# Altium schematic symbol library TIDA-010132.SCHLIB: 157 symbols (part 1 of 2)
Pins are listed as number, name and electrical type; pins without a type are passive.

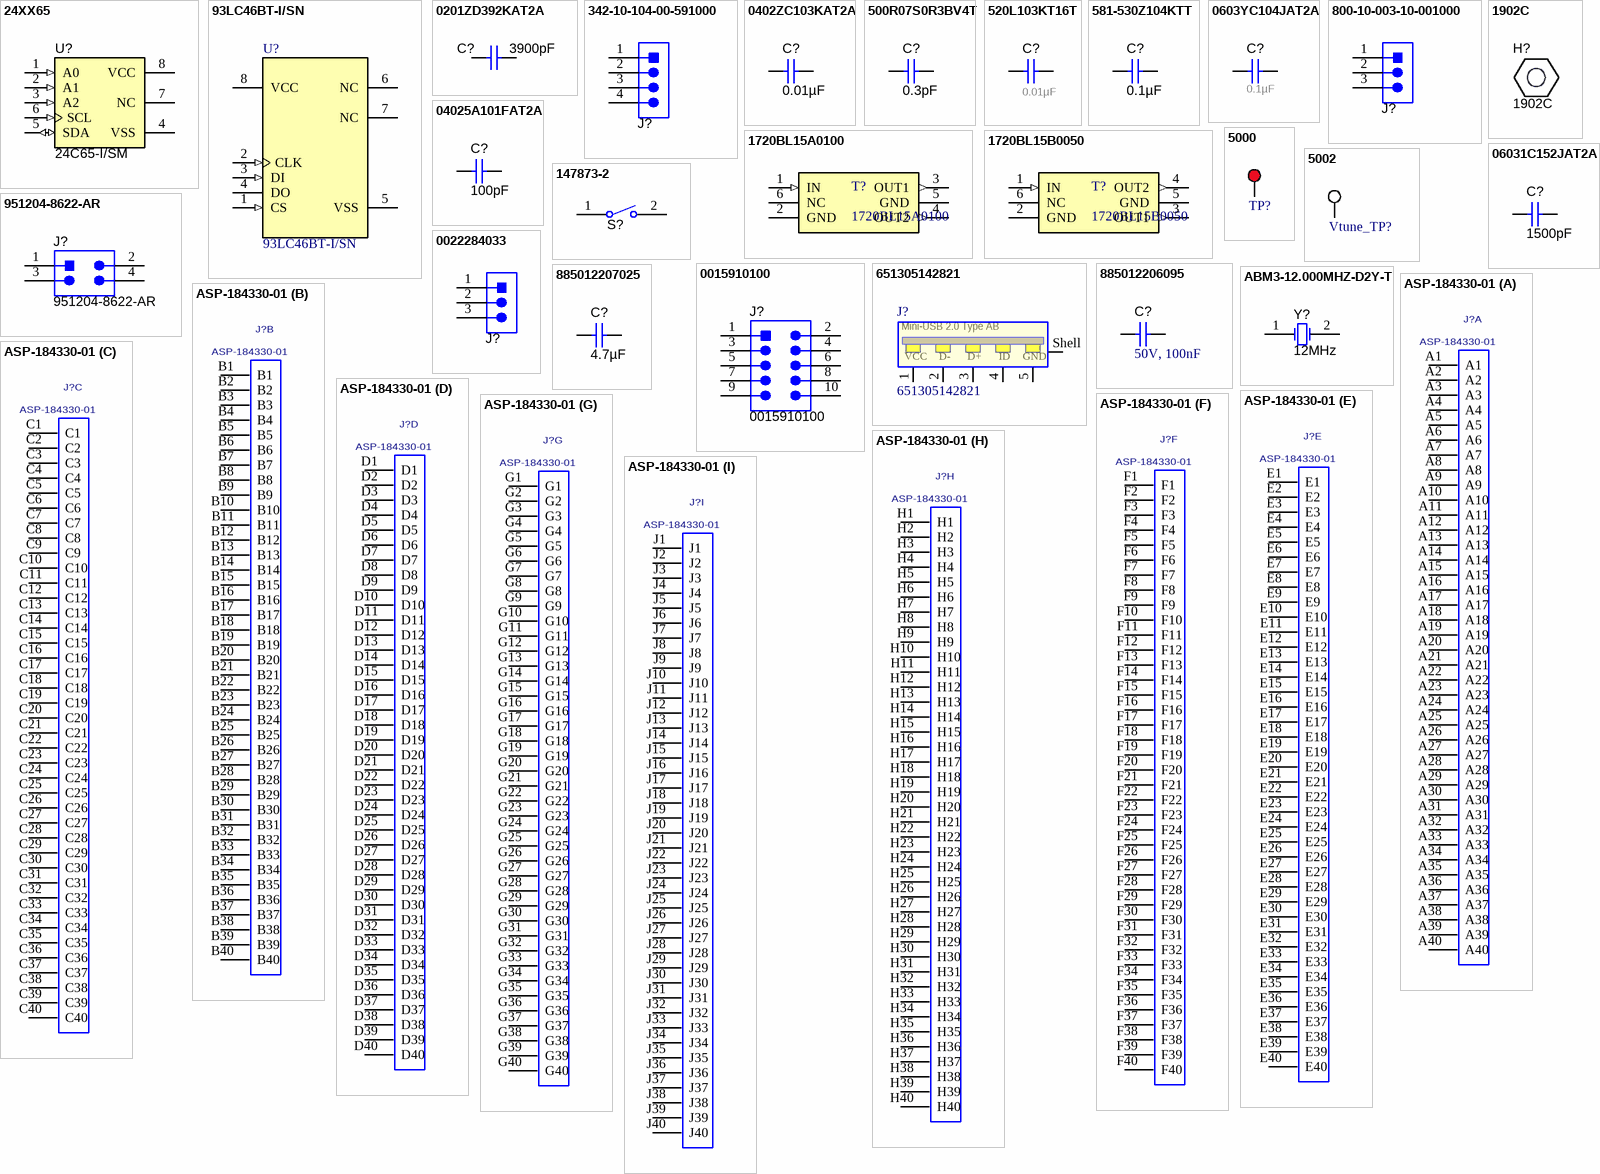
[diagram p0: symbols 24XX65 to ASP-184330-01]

## 24XX65
designator U?, comment 24C65-I/SM
64K I2C Smart Serial EEPROM, SOIC-8; Manufacturer: Microchip
footprint SOIC127P800X216-8N (SOIC, 8-Leads, Body 5.3x5.3mm (max), Pitch 1.27mm, IPC Medium Density)
footprint SOIC127P800X216-8L (SOIC, 8-Leads, Body 5.3x5.3mm (max), Pitch 1.27mm, IPC High Density)
footprint SOIC127P800X216-8M (SOIC, 8-Leads, Body 5.3x5.3mm (max), Pitch 1.27mm, IPC Low Density)
pins: 1 A0 (in), 2 A1 (in), 3 A2 (in), 4 VSS (power), 5 SDA (io), 6 SCL (in), 7 NC, 8 VCC (power)

## 93LC46BT-I/SN
designator U?
1K Microwire Compatible Serial EEPROM; Manufacturer: Microchip; SymbolCreator: Altium; SizeAreaWB_mm2: 55.131; SizeArea_mm2: 29.351; SizeX_mm: 5.99; SizeY_mm: 4.9; SizeZ_mm: 1.75
footprint SOIC-8
footprint SOIC-8M
footprint SOIC-8L
pins: 1 CS (in), 2 CLK (in), 3 DI (in), 4 DO (hiz), 5 VSS (power), 6 NC, 7 NC, 8 VCC (power)

## 0201ZD392KAT2A
designator C?  ValueDisplayed: 3900pF  (hidden comment: 0201ZD392KAT2A)
CAP, CERM, 3900 pF, 10 V, +/- 10%, X5R, 0201; Manufacturer: AVX; Polarized: N; CompType: Capacitor; Value: 3900pF; U/M: EA; Cap_F: 0.0000000039; Tolerance_%: 10; Value1: Unknown; Value2: 10V; TaMin_C: -55; TaMax_C: 85; Cap_Case: 0201; SizeArea_mm2: 0.18; SizeAreaWB_mm2: 2.08; SizeX_mm: 0.6; SizeY_mm: 0.3; SizeZ_mm: 0.26; AEC Category: Q200
signal-integrity model Cap
simulation model Cap
footprint 0201
footprint 0201M
footprint 0201L
footprint 0201_Silk
pins: 1, 2

## 342-10-104-00-591000
designator J?  (value not drawn)
Header, 100mil, 4x1, Gold, TH; Manufacturer: Mill-Max; SymbolCreator: a0412235; Green_Lifecycle: Active; Green_REACh: Passed
footprint Mill-Max_342-xx-104-00-591000
pins: 1, 2, 3, 4

## 0402ZC103KAT2A
designator C?  ValueDisplayed: 0.01µF  (hidden comment: 0402ZC103KAT2A)
CAP, CERM, 0.01 µF, 10 V,+/- 10%, X7R, 0402; Manufacturer: AVX; Polarized: N; CompType: Capacitor; Value: 0.01uF; U/M: EA; Cap_F: 0.00000001; Tolerance_%: 10; Value2: 10V; TaMin_C: -55; TaMax_C: 125; Cap_Case: 0402; SizeArea_mm2: 0.5; SizeAreaWB_mm2: 3; SizeX_mm: 1; SizeZ_mm: 0.6; AEC Category: Q200
signal-integrity model Cap
simulation model Cap
footprint 0402
footprint 0402M
footprint 0402L
footprint 0402S
pins: 1, 2

## 500R07S0R3BV4T
designator C?  ValueDisplayed: 0.3pF  (hidden comment: 500R07S0R3BV4T)
CAP, CERM, 0.3 pF, 50 V,+/- 30%, C0G/NP0, 0402; Manufacturer: Johanson Technology; Polarized: N; CompType: Capacitor; Value: 0.3pF; U/M: EA; Cap_F: 0.0000000000003; Tolerance_%: 30; Value1: Unknown; VDC_V: 50; Value2: 50V; TaMin_C: -55; TaMax_C: 125; Cap_Case: 0402; SizeArea_mm2: 0.5; SizeAreaWB_mm2: 3; SizeX_mm: 1; SizeZ_mm: 0.6; AEC Category: Q200
signal-integrity model Cap
simulation model Cap
footprint 0402
footprint 0402M
footprint 0402L
footprint 0402S
pins: 1, 2

## 520L103KT16T
designator C?  ValueDisplayed: 0.01µF  (hidden comment: 520L103KT16T)
CAP, CERM, 0.01 µF, 16 V, +/- 10%, X7R, 0402; Manufacturer: AT Ceramics; Polarized: N; CompType: Capacitor; Value: 0.01uF; U/M: EA; Cap_F: 0.00000001; Tolerance_%: 10; Value1: Unknown; VDC_V: 16; Value2: 16V; TaMin_C: -55; TaMax_C: 125; Cap_Case: 0402; AEC Category: Q200; SizeArea_mm2: 0.5; SizeAreaWB_mm2: 3; SizeX_mm: 1; SizeZ_mm: 0.65
signal-integrity model Cap
simulation model Cap
footprint 0402_065
footprint 0402_065M
footprint 0402_065L
footprint 0402_065S
pins: 1, 2

## 581-530Z104KTT
designator C?, comment ValueDisplayed: 0.1µF  (hidden comment: 530Z104KT10T)
Multilayer Ceramic Capacitors MLCC - SMD/SMT 10volts 0.1uF 10%; Manufacturer: ATC; Polarized: N; U/M: EA; Cap_F: 0.0000001; Tolerance_%: 10; Value1: Unknown; Value2: 10V; TempCo: X7S; TaMin_C: -55; TaMax_C: 125; Cap_Case: 0201; SizeArea_mm2: 0.18; SizeAreaWB_mm2: 2.08; SizeX_mm: 0.6; SizeY_mm: 0.3; SizeZ_mm: 0.26; AEC Category: Q200
signal-integrity model Cap
simulation model Cap
footprint 0201
footprint 0201M
footprint 0201L
footprint 0201_Silk
footprint 0201_afe
pins: 1, 2

## 0603YC104JAT2A
designator C?  ValueDisplayed: 0.1µF  (hidden comment: 0603YC104JAT2A)
CAP, CERM, 0.1uF, 16V, +/-5%, X7R, 0603; Manufacturer: AVX; Cap_Case: 0603; ESR_Ohm: 0.039; Polarized: N; TaMax_C: 125; TaMin_C: -55; Tolerance_%: 5; VDC_V: 16; Cap_F: 0.0000001; CompType: Capacitor; Value1: 0.039 ohm; U/M: EA
signal-integrity model Cap
simulation model Cap
footprint 0603
footprint 0603M
footprint 0603L
footprint 0603_HV
pins: 1, 2

## 800-10-003-10-001000
designator J?  (value not drawn)
Header, 100mil, 3x1, TH; Manufacturer: Mill-Max; SymbolCreator: a0799628
footprint Mill-Max_800-10-003-10-001000
pins: 1, 2, 3
3 alternate drawings of the same symbol

## 1720BL15A0100
designator T?
BALUN 625MHZ-2.8GHZ 50/100 0805; PartNumber: 1720BL15A0100E; Manufacturer: Johanson Technology Inc.
pins: 1 IN (in), 2 GND (power), 3 OUT1 (out), 4 OUT2 (out), 5 GND (power), 6 NC (hiz)

## 1720BL15B0050
designator T?
BALUN 625MHZ-2.8GHZ 50/50 0805; PartNumber: 1720BL15B0050E; Manufacturer: Johanson Technology Inc.
pins: 1 IN (in), 2 GND (power), 3 OUT1 (out), 4 OUT2 (out), 5 GND (power), 6 NC (hiz)

## 1902C
designator H?
Standoff, Hex, 0.5"L #4-40 Nylon; Manufacturer: Keystone; Green_Lifecycle: Active; Green_REACh: Passed; SymbolCreator: a0412235
footprint Keystone_1902C

## 04025A101FAT2A
designator C?  ValueDisplayed: 100pF  (hidden comment: 04025A101FAT2A)
CAP, CERM, 100 pF, 50 V, +/- 1%, C0G/NP0, 0402; Manufacturer: AVX; Polarized: N; CompType: Capacitor; Value: 100pF; U/M: EA; Cap_F: 0.0000000001; Tolerance_%: 1; Value1: Unknown; VDC_V: 50; Value2: 50V; TaMin_C: -55; TaMax_C: 125; Cap_Case: 0402; SizeArea_mm2: 0.5; SizeAreaWB_mm2: 3; SizeZ_mm: 0.6; AEC Category: Q200
signal-integrity model Cap
simulation model Cap
footprint 0402
footprint 0402M
footprint 0402L
footprint 0402S
pins: 1, 2

## 5000
designator TP?  (value not drawn)
Test Point, Miniature, Red, TH; Manufacturer: Keystone; CompType: Test Point Loop; ContactFinish: Silver; Green_Lifecycle: Active; Green_REACh: Passed
footprint Keystone5000
pins: 1

## 5002
designator Vtune_TP?  (value not drawn)
Test Point, Miniature, White, TH; Manufacturer: Keystone; CompType: Test Point Loop; ContactFinish: Silver; Green_Lifecycle: Active; Green_REACh: Passed
footprint Keystone5002
pins: 1

## 06031C152JAT2A
designator C?  ValueDisplayed: 1500pF  (hidden comment: 06031C152JAT2A)
CAP, CERM, 1500 pF, 100 V, +/- 5%, X7R, 0603; Manufacturer: AVX; Cap_Case: 0603; ESR_ohm: 0.229; Polarized: N; TaMax_C: 125; TaMin_C: -55; Tolerance_%: 5; VDC_V: 100; Cap_F: 0.0000000015; CompType: Capacitor; Value: 1500pF; Value1: 0.229 ohm; Value2: 100V; U/M: EA; AEC Category: Q200; SizeArea_mm2: 1.28; SizeAreaWB_mm2: 4.68; SizeX_mm: 1.6; SizeY_mm: 0.8; SizeZ_mm: 1
signal-integrity model Cap
simulation model Cap
footprint 0603
footprint 0603M
footprint 0603L
footprint 0603_HV
footprint 0603S
pins: 1, 2

## 147873-2
designator S?  (value not drawn)
Switch, SPST, Off-On, 50 mA,24V, SMD; Manufacturer: TE Connectivity; SymbolCreator: a0799628; SizeAreaWB_mm2: 48.4; SizeArea_mm2: 23.8; SizeX_mm: 6.8; SizeY_mm: 3.5; SizeZ_mm: 4.65; VDC_V: 24; PositionCount: 1; CurrentRating_mA: 50
footprint SW_147873-2
pins: 1, 2

## 951204-8622-AR
designator J?
Header, 2mm, 2x2, Gold, TH; Manufacturer: 3M; SymbolCreator: a0412235; Pitch_mm: 2; Gender: Male; Shrouded: N; Current_A: 1; Voltage_V: 1000; Cert_UL: Y
footprint 3M_951204-8622
pins: 1, 2, 3, 4

## 0015910100
designator J?
Header, 100mil, 5x2, SMT; Manufacturer: Molex; SymbolCreator: a0412235; Green_Lifecycle: Active; Green_REACh: Passed
footprint Molex_0015910100
pins: 1, 2, 3, 4, 5, 6, 7, 8, 9, 10

## 0022284033
designator J?  (value not drawn)
Header, 2.54mm, 3x1, Tin, TH; Manufacturer: Molex; SymbolCreator: a0799628; Pitch_mm: 2.54; Gender: Male; Shrouded: N; Row_Count: 1; Current_A: 4; Voltage_V: 250; Cert_UL: Y
footprint Molex_0022284033
pins: 1, 2, 3
3 alternate drawings of the same symbol

## 651305142821
designator J?
WR-COM Mini USB 2.0 Type AB SMT Horizontal 5 Contacts
footprint 651305142821 (5 pins)
pins: 1 VCC, 2 D-, 3 D+, 4 ID, 5 GND, Shell

## 885012206095
designator C?, comment 50V, 100nF
WCAP-CSGP Ceramic Capacitors, 0603, X7R, 50V, 100nF; Part Number: 885012206095; Manufacturer: Wurth Electronics Inc.; Rated Voltage: 50V DC
footprint 0603_1.6x0.8x0.8mm_Wave Soldering
footprint 0603_1.6x0.8x0.8mm_Reflow Soldering
pins: 1, 2

## 885012207025
designator C?  ValueDisplayed: 4.7µF  (hidden comment: 885012207025)
CAP, CERM, 4.7 µF, 10 V,+/- 10%, X7R, 0805; Manufacturer: Wurth Elektronik; Polarized: N; CompType: Capacitor; Value: 4.7uF; U/M: EA; Cap_F: 0.0000047; Tolerance_%: 10; Value2: 10V; TaMin_C: -55; TaMax_C: 125; Cap_Case: 0805; SizeArea_mm2: 2.5; SizeAreaWB_mm2: 6.75; SizeX_mm: 2; SizeY_mm: 1.25; SizeZ_mm: 1.45; AEC Category: Q200
signal-integrity model Cap
simulation model Cap
footprint 0805_HV
footprint 0805_HV1
footprint 0805
footprint 0805M
footprint 0805L
pins: 1, 2

## ABM3-12.000MHZ-D2Y-T
designator Y?  Frequency: 12MHz  (hidden comment: ABM3-12.000MHZ-D2Y-T)
Crystal, 12 MHz, 18 pF, SMD; Manufacturer: Abracon Corporation; SymbolCreator: a0412235; U/M: EA; TaMin_C: -40; TaMax_C: 85; Frequency Stability: ±30ppm
footprint XTAL_ABM3
pins: 1 OSC1, 2 OSC2

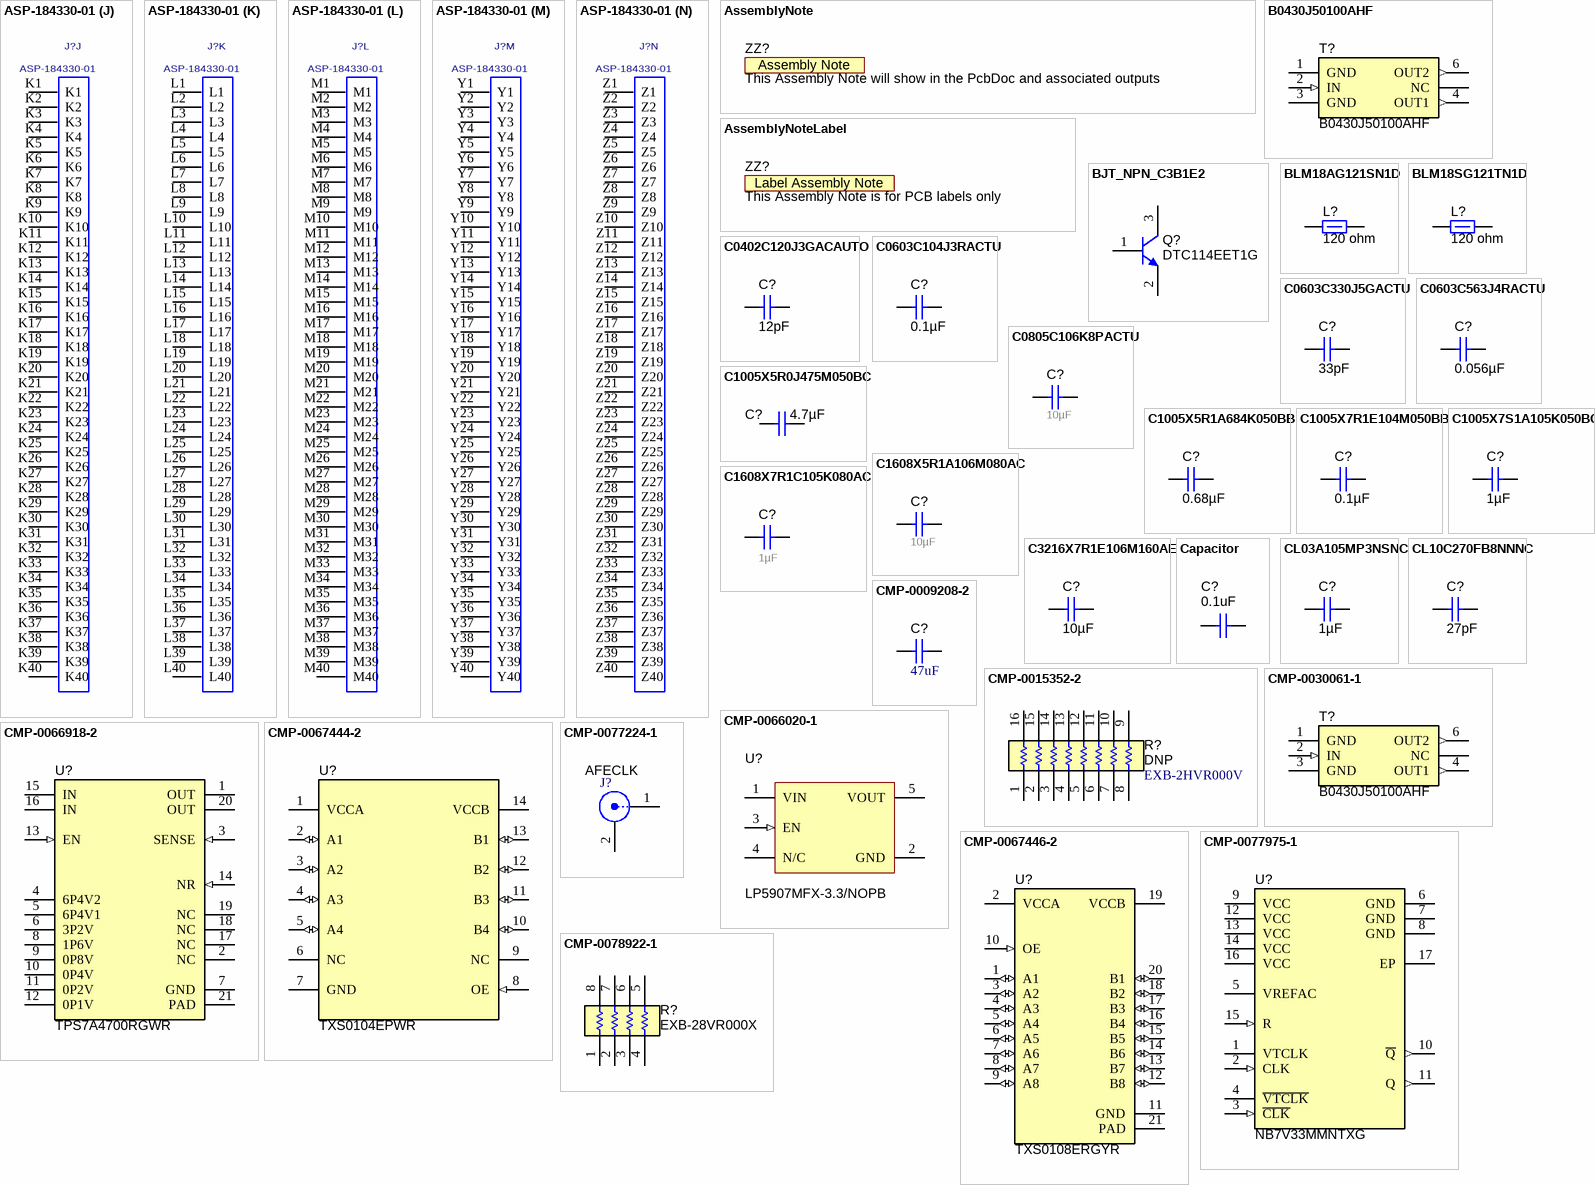
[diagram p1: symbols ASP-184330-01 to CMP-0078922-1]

## ASP-184330-01
designator J?
14 ROW .050 PITCH TERMINAL ARRAY ASM.; Manufacturer: SAMTEC
footprint ASP-184330-01 (Terminal Array, 1.27mm, 40x14, SMT)
part A pins: A1, A2, A3, A4, A5, A6, A7, A8, A9, A10, A11, A12, A13, A14, A15, A16, A17, A18, A19, A20, A21, A22, A23, A24, A25, A26, A27, A28, A29, A30, A31, A32, A33, A34, A35, A36, A37, A38, A39, A40
part B pins: B1, B2, B3, B4, B5, B6, B7, B8, B9, B10, B11, B12, B13, B14, B15, B16, B17, B18, B19, B20, B21, B22, B23, B24, B25, B26, B27, B28, B29, B30, B31, B32, B33, B34, B35, B36, B37, B38, B39, B40
part C pins: C1, C2, C3, C4, C5, C6, C7, C8, C9, C10, C11, C12, C13, C14, C15, C16, C17, C18, C19, C20, C21, C22, C23, C24, C25, C26, C27, C28, C29, C30, C31, C32, C33, C34, C35, C36, C37, C38, C39, C40
part D pins: D1, D2, D3, D4, D5, D6, D7, D8, D9, D10, D11, D12, D13, D14, D15, D16, D17, D18, D19, D20, D21, D22, D23, D24, D25, D26, D27, D28, D29, D30, D31, D32, D33, D34, D35, D36, D37, D38, D39, D40
part E pins: E1, E2, E3, E4, E5, E6, E7, E8, E9, E10, E11, E12, E13, E14, E15, E16, E17, E18, E19, E20, E21, E22, E23, E24, E25, E26, E27, E28, E29, E30, E31, E32, E33, E34, E35, E36, E37, E38, E39, E40
part F pins: F1, F2, F3, F4, F5, F6, F7, F8, F9, F10, F11, F12, F13, F14, F15, F16, F17, F18, F19, F20, F21, F22, F23, F24, F25, F26, F27, F28, F29, F30, F31, F32, F33, F34, F35, F36, F37, F38, F39, F40
part G pins: G1, G2, G3, G4, G5, G6, G7, G8, G9, G10, G11, G12, G13, G14, G15, G16, G17, G18, G19, G20, G21, G22, G23, G24, G25, G26, G27, G28, G29, G30, G31, G32, G33, G34, G35, G36, G37, G38, G39, G40
part H pins: H1, H2, H3, H4, H5, H6, H7, H8, H9, H10, H11, H12, H13, H14, H15, H16, H17, H18, H19, H20, H21, H22, H23, H24, H25, H26, H27, H28, H29, H30, H31, H32, H33, H34, H35, H36, H37, H38, H39, H40
part I pins: J1, J2, J3, J4, J5, J6, J7, J8, J9, J10, J11, J12, J13, J14, J15, J16, J17, J18, J19, J20, J21, J22, J23, J24, J25, J26, J27, J28, J29, J30, J31, J32, J33, J34, J35, J36, J37, J38, J39, J40
part J pins: K1, K2, K3, K4, K5, K6, K7, K8, K9, K10, K11, K12, K13, K14, K15, K16, K17, K18, K19, K20, K21, K22, K23, K24, K25, K26, K27, K28, K29, K30, K31, K32, K33, K34, K35, K36, K37, K38, K39, K40
part K pins: L1, L2, L3, L4, L5, L6, L7, L8, L9, L10, L11, L12, L13, L14, L15, L16, L17, L18, L19, L20, L21, L22, L23, L24, L25, L26, L27, L28, L29, L30, L31, L32, L33, L34, L35, L36, L37, L38, L39, L40
part L pins: M1, M2, M3, M4, M5, M6, M7, M8, M9, M10, M11, M12, M13, M14, M15, M16, M17, M18, M19, M20, M21, M22, M23, M24, M25, M26, M27, M28, M29, M30, M31, M32, M33, M34, M35, M36, M37, M38, M39, M40
part M pins: Y1, Y2, Y3, Y4, Y5, Y6, Y7, Y8, Y9, Y10, Y11, Y12, Y13, Y14, Y15, Y16, Y17, Y18, Y19, Y20, Y21, Y22, Y23, Y24, Y25, Y26, Y27, Y28, Y29, Y30, Y31, Y32, Y33, Y34, Y35, Y36, Y37, Y38, Y39, Y40
part N pins: Z1, Z2, Z3, Z4, Z5, Z6, Z7, Z8, Z9, Z10, Z11, Z12, Z13, Z14, Z15, Z16, Z17, Z18, Z19, Z20, Z21, Z22, Z23, Z24, Z25, Z26, Z27, Z28, Z29, Z30, Z31, Z32, Z33, Z34, Z35, Z36, Z37, Z38, Z39, Z40

## AssemblyNote
designator ZZ?, comment This Assembly Note will show in the PcbDoc and associated outputs  (no BOM)
SymbolCreator: codlsc
footprint AssemblyNote

## AssemblyNoteLabel
designator ZZ?, comment This Assembly Note is for PCB labels only  (no BOM)
SymbolCreator: a0412235
footprint AssemblyNoteLabel

## B0430J50100AHF
designator T?
Transformer, Multi-layer balun, SMD; Manufacturer: Anaren; Green_REACh: Incomplete; Green_Lifecycle: Not Set
footprint B0430J50100AHF (Anaren Ultra Low Profile 0805 Balun 50  to 100  Balanced)
pins: 1 GND (power), 2 IN (in), 3 GND (power), 4 OUT1 (out), 5 NC (hiz), 6 OUT2 (out)

## BJT_NPN_C3B1E2
designator Q?, comment DTC114EET1G
Transistor, NPN, 50 V, 0.1 A, AEC-Q101, SOT-416; Manufacturer: ON Semiconductor; TaMax_C: 150°C; Value2: 60; Value1: 0.1 A; Vcesat1_V: 2.5dV; SizeX_mm: 1.6; TaMin_C: -55°C; IcRated_A: 1dA; CompType: BJT; SizeZ_mm: 0.95; AEC Qualified: Y; Value: 50 V; SizeArea_mm2: 2.56; NPN: 1; Vceo_V: 50V; PNP: 0; AEC Category: Q101; SizeAreaWB_mm2: 6.76; U/M: EA
footprint SOT-416 (NXP recommended footprint.)
pins: 1 B, 2 E, 3 C

## BLM18AG121SN1D
designator L?  ValueDisplayed: 120 ohm  (hidden comment: BLM18AG121SN1D)
Ferrite Bead, 120 ohm @ 100 MHz, 0.5 A, 0603; Manufacturer: MuRata; Value: 120 ohm; Imax_A: 0.5; DCR_ohm: 0.18; Value1: 0.18 ohm; Value2: 0.5A; SizeAreaWB_mm2: 4.68; SizeArea_mm2: 1.28; SizeX_mm: 1.6; SizeY_mm: 0.8; SizeZ_mm: 1; ZTyp@100MHz_Ohm: 120
footprint 0603
footprint 0603M
footprint 0603L
footprint 0603_HV
footprint 0603S
pins: 1, 2

## BLM18SG121TN1D
designator L?  ValueDisplayed: 120 ohm  (hidden comment: BLM18SG121TN1D)
Ferrite Bead, 120 ohm @ 100 MHz, 3 A, 0603; Manufacturer: MuRata; Value: 120 ohm; Imax_A: 3; DCR_ohm: 0.025; Value1: 0.025 ohm; Value2: 3A; SizeAreaWB_mm2: 4.68; SizeArea_mm2: 1.28; SizeX_mm: 1.6; SizeY_mm: 0.8; SizeZ_mm: 1; ZTyp@100MHz_Ohm: 120
footprint 0603
footprint 0603M
footprint 0603L
footprint 0603_HV
footprint 0603S
pins: 1, 2

## C0402C120J3GACAUTO
designator C?  ValueDisplayed: 12pF  (hidden comment: C0402C120J3GACAUTO)
CAP, CERM, 12 pF, 25 V, +/- 5%, C0G/NP0, AEC-Q200 Grade 1, 0402; Manufacturer: Kemet; Polarized: N; CompType: Capacitor; Value: 12pF; U/M: EA; Cap_F: 0.000000000012; Tolerance_%: 5; Value1: Unknown; VDC_V: 25; Value2: 25V; TaMin_C: -55; TaMax_C: 125; Cap_Case: 0402; SizeArea_mm2: 0.5; SizeAreaWB_mm2: 3; SizeX_mm: 1; SizeZ_mm: 0.6; AEC Category: Q200; AEC Qualified: Y
signal-integrity model Cap
simulation model Cap
footprint 0402
footprint 0402M
footprint 0402L
footprint 0402S
pins: 1, 2

## C0603C104J3RACTU
designator C?  ValueDisplayed: 0.1µF  (hidden comment: C0603C104J3RACTU)
CAP, CERM, 0.1uF, 25V, +/-5%, X7R, 0603; Manufacturer: Kemet; Cap_Case: 0603; Polarized: N; TaMax_C: 125; TaMin_C: -55; Tolerance_%: 5; VDC_V: 25; Cap_F: 0.0000001; CompType: Capacitor; Value1: Unknown; U/M: EA
signal-integrity model Cap
simulation model Cap
footprint 0603
footprint 0603M
footprint 0603L
footprint 0603_HV
pins: 1, 2

## C0603C330J5GACTU
designator C?  ValueDisplayed: 33pF  (hidden comment: C0603C330J5GACTU)
CAP, CERM, 33pF, 50V, +/-5%, C0G/NP0, 0603; Manufacturer: Kemet; Cap_Case: 0603; Polarized: N; TaMax_C: 125; TaMin_C: -55; Tolerance_%: 5; VDC_V: 50; Cap_F: 0.000000000033; CompType: Capacitor; U/M: EA; Value1: Unknown
signal-integrity model Cap
simulation model Cap
footprint 0603
footprint 0603M
footprint 0603L
footprint 0603_HV
pins: 1, 2

## C0603C563J4RACTU
designator C?  ValueDisplayed: 0.056µF  (hidden comment: C0603C563J4RACTU)
CAP, CERM, 0.056 µF, 16 V, +/- 5%, X7R, 0603; Manufacturer: Kemet; Cap_Case: 0603; Polarized: N; TaMax_C: 125; TaMin_C: -55; Tolerance_%: 5; VDC_V: 16; Cap_F: 0.000000056; CompType: Capacitor; Value: 0.056uF; Value1: Unknown; Value2: 16V; U/M: EA; AEC Category: Q200; SizeArea_mm2: 1.28; SizeAreaWB_mm2: 4.68; SizeX_mm: 1.6; SizeY_mm: 0.8; SizeZ_mm: 1
signal-integrity model Cap
simulation model Cap
footprint 0603
footprint 0603M
footprint 0603L
footprint 0603_HV
footprint 0603S
pins: 1, 2

## C0805C106K8PACTU
designator C?  ValueDisplayed: 10µF  (hidden comment: C0805C106K8PACTU)
CAP, CERM, 10uF, 10V, +/-10%, X5R, 0805; Manufacturer: Kemet; Cap_Case: 0805; ESR_Ohm: 0.003; IRMS_A: 11.43; Polarized: N; TaMax_C: 85; TaMin_C: -55; Tolerance_%: 10; Cap_F: 0.00001; CompType: Capacitor; U/M: EA; Value1: 0.003 ohm
signal-integrity model Cap
simulation model Cap
footprint 0805_HV
footprint 0805
footprint 0805M
footprint 0805L
pins: 1, 2

## C1005X5R0J475M050BC
designator C?  ValueDisplayed: 4.7µF  (hidden comment: C1005X5R0J475M050BC)
CAP, CERM, 4.7 µF, 6.3 V, +/- 20%, X5R, 0402; Manufacturer: TDK; Polarized: N; CompType: Capacitor; Value: 4.7uF; U/M: EA; Cap_F: 0.0000047; Tolerance_%: 20; Value1: Unknown; VDC_V: 6.3; Value2: 6.3V; TaMin_C: -55; TaMax_C: 85; Cap_Case: 0402; SizeArea_mm2: 0.5; SizeAreaWB_mm2: 3; SizeX_mm: 1; SizeZ_mm: 0.6; AEC Category: Q200
signal-integrity model Cap
simulation model Cap
footprint 0402
footprint 0402M
footprint 0402L
footprint 0402S
pins: 1, 2

## C1005X5R1A684K050BB
designator C?  ValueDisplayed: 0.68µF  (hidden comment: C1005X5R1A684K050BB)
CAP, CERM, 0.68 µF, 10 V, +/- 10%, X5R, 0402; Manufacturer: TDK; Polarized: N; CompType: Capacitor; Value: 0.68uF; U/M: EA; Cap_F: 0.00000068; Tolerance_%: 10; Value1: Unknown; Value2: 10V; TaMin_C: -55; TaMax_C: 85; Cap_Case: 0402; SizeArea_mm2: 0.5; SizeAreaWB_mm2: 3; SizeX_mm: 1; SizeZ_mm: 0.6; AEC Category: Q200
signal-integrity model Cap
simulation model Cap
footprint 0402
footprint 0402M
footprint 0402L
footprint 0402S
pins: 1, 2

## C1005X7R1E104M050BB
designator C?  ValueDisplayed: 0.1µF  (hidden comment: C1005X7R1E104M050BB)
CAP, CERM, 0.1 µF, 25 V, +/- 20%, X7R, 0402; Manufacturer: TDK; Cap_Case: 0402; Polarized: N; TaMax_C: 125; TaMin_C: -55; Tolerance_%: 20; VDC_V: 25; Cap_F: 0.0000001; CompType: Capacitor; Value: 0.1uF; Value1: Unknown; Value2: 25V; U/M: EA; SizeArea_mm2: 0.5; SizeAreaWB_mm2: 3; SizeX_mm: 1; SizeZ_mm: 0.6; AEC Category: Q200
signal-integrity model Cap
simulation model Cap
footprint 0402
footprint 0402M
footprint 0402L
footprint 0402S
pins: 1, 2

## C1005X7S1A105K050BC
designator C?  ValueDisplayed: 1µF  (hidden comment: C1005X7S1A105K050BC)
CAP, CERM, 1 µF, 10 V, +/- 10%, X7S, 0402; Manufacturer: TDK; Polarized: N; CompType: Capacitor; Value: 1uF; U/M: EA; Cap_F: 0.000001; Tolerance_%: 10; ESR_ohm: 0.011416; Value1: 0.011416 ohm; Value2: 10V; IRMS_A: 1.483; TaMin_C: -55; TaMax_C: 125; Cap_Case: 0402; SizeArea_mm2: 0.5; SizeAreaWB_mm2: 3; SizeX_mm: 1; SizeZ_mm: 0.6; AEC Category: Q200
signal-integrity model Cap
simulation model Cap
footprint 0402
footprint 0402M
footprint 0402L
footprint 0402S
pins: 1, 2

## C1608X5R1A106M080AC
designator C?  ValueDisplayed: 10µF  (hidden comment: C1608X5R1A106M080AC)
CAP, CERM, 10 µF, 10 V, +/- 20%, X5R, 0603; Manufacturer: TDK; Cap_Case: 0603; ESR_ohm: 0.0078; IRMS_A: 1.85; Polarized: N; TaMax_C: 85; TaMin_C: -55; Tolerance_%: 20; VDC_V: 10; Cap_F: 0.00001; CompType: Capacitor; Value: 10uF; U/M: EA; Value1: 0.0078 ohm; Value2: 10V; AEC Category: Q200
signal-integrity model Cap
simulation model Cap
footprint 0603
footprint 0603M
footprint 0603L
footprint 0603_HV
footprint 0603S
pins: 1, 2

## C1608X7R1C105K080AC
designator C?  ValueDisplayed: 1µF  (hidden comment: C1608X7R1C105K080AC)
CAP, CERM, 1 µF, 16 V, +/- 10%, X7R, 0603; Manufacturer: TDK; Cap_Case: 0603; ESR_ohm: 0.0057; Polarized: N; TaMax_C: 125; TaMin_C: -55; Tolerance_%: 10; VDC_V: 16; Cap_F: 0.000001; CompType: Capacitor; Value: 1uF; Value1: 0.0057 ohm; Value2: 16V; U/M: EA; SizeArea_mm2: 1.28; SizeAreaWB_mm2: 4.68; SizeX_mm: 1.6; SizeY_mm: 0.8; SizeZ_mm: 1; AEC Category: Q200
signal-integrity model Cap
simulation model Cap
footprint 0603
footprint 0603M
footprint 0603L
footprint 0603_HV
footprint 0603S
pins: 1, 2

## C3216X7R1E106M160AE
designator C?  ValueDisplayed: 10µF  (hidden comment: C3216X7R1E106M160AE)
CAP, CERM, 10 µF, 25 V, +/- 20%, X7R, 1206_190; Manufacturer: TDK; Polarized: N; CompType: Capacitor; Value: 10uF; U/M: EA; Cap_F: 0.00001; Tolerance_%: 20; Value1: Unknown; VDC_V: 25; Value2: 25V; TaMin_C: -55; TaMax_C: 125; Cap_Case: 1206; SizeArea_mm2: 5.12; SizeAreaWB_mm2: 10.92; SizeX_mm: 3.2; SizeY_mm: 1.6; SizeZ_mm: 1.9; AEC Category: Q200
signal-integrity model Cap
simulation model Cap
footprint 1206_190
footprint 1206_190M
footprint 1206_190L
pins: 1, 2

## Capacitor
designator C?, comment ValueDisplayed: 0.1uF  (hidden comment: 550L104KCAT)
CAP, CERM, 0.1 uF, 16 V, +/- 10%, Unknown, 0402; Manufacturer: AT Ceramics; TaMin_C: -55°C; Polarized: N; SizeAreaWB_mm2: 3; U/M: EA; Value: 0.1uF; TaMax_C: 125°C; SizeZ_mm: 0.65; SizeX_mm: 1; SizeY_mm: 0.5; Cap_Case: 0402; Value2: 16V; CompType: Capacitor; Cap_F: 100nF; AEC Category: Q200
footprint 0402_065 (0402)
footprint 0402_065S (Based on C0402S footprint from PADS legacy)
footprint 0402_065L (0402)
footprint 0402_065M (0402)
pins: 1, 2

## CL03A105MP3NSNC
designator C?  ValueDisplayed: 1µF  (hidden comment: CL03A105MP3NSNC)
CAP, CERM, 1 µF, 10 V,+/- 20%, X5R, 0201; Manufacturer: Samsung Electro-Mechanics; Polarized: N; CompType: Capacitor; Value: 1uF; U/M: EA; Cap_F: 0.000001; Tolerance_%: 20; VDC_V: 10; Value2: 10V; TaMin_C: -55; TaMax_C: 85; Cap_Case: 0201; SizeArea_mm2: 0.18; SizeAreaWB_mm2: 2.08; SizeX_mm: 0.6; SizeY_mm: 0.3; SizeZ_mm: 0.26; AEC Category: Q200; Green_Lifecycle: Active; Green_REACh: Passed
signal-integrity model Cap
simulation model Cap
footprint 0201
footprint 0201M
footprint 0201L
footprint 0201_Silk
pins: 1, 2

## CL10C270FB8NNNC
designator C?  ValueDisplayed: 27pF  (hidden comment: CL10C270FB8NNNC)
CAP, CERM, 27 pF, 50 V,+/- 1%, C0G/NP0, 0603; Manufacturer: Samsung Electro-Mechanics; Polarized: N; CompType: Capacitor; Value: 27pF; U/M: EA; Cap_F: 0.000000000027; Tolerance_%: 1; VDC_V: 50; Value2: 50V; TaMin_C: -55; TaMax_C: 125; Cap_Case: 0603; SizeArea_mm2: 1.28; SizeAreaWB_mm2: 4.68; SizeX_mm: 1.6; SizeY_mm: 0.8; AEC Category: Q200; Green_Lifecycle: Active; Green_REACh: Passed
signal-integrity model Cap
simulation model Cap
footprint 0603
footprint 0603M
footprint 0603L
footprint 0603_HV
footprint 0603S
pins: 1, 2

## CMP-0009208-2
designator C?, comment value 47uF  (hidden comment: GRM32ER61A476KE20L)
CAP, CERM, 47 uF, 10 V, +/- 10%, X5R, 1210; Manufacturer: MuRata; TaMin_C: -55°C; ESR_ohm: 1m; Polarized: N; SizeAreaWB_mm2: 14.7; Value1: 0.001 ohm; U/M: EA; TaMax_C: 85°C; SizeZ_mm: 2.7; SizeX_mm: 3.2; SizeY_mm: 2.5; Cap_Case: 1210; Value2: 10V; SizeArea_mm2: 8; CompType: Capacitor; Cap_F: 47µF; AEC Category: Q200
footprint 1210_270 (1210)
footprint 1210_270L (1210)
footprint 1210_270M (1210)
pins: 1, 2

## CMP-0015352-2
designator R?, comment DNP  PartNumber: EXB-2HVR000V
RES, 0, 5%, 0.0625 W, Resistor Array - 8x1; Manufacturer: Panasonic; Power_W: 62.5mW; TempCo: ppm/C; Value_Code: 0000; U/M: EA; Value: 0; EIA_Code: E24; AEC Category: Q200
footprint RESCAXS_EXB-2HV (Panasonic Resistor Array)
pins: 1, 2, 3, 4, 5, 6, 7, 8, 9, 10, 11, 12, 13, 14, 15, 16

## CMP-0030061-1
designator T?, comment B0430J50100AHF
Transformer, Multi-layer balun, SMD; Manufacturer: Anaren; Green_REACh: Incomplete; Green_Lifecycle: Not Set
footprint B0430J50100AHF (Anaren Ultra Low Profile 0805 Balun 50  to 100  Balanced)
pins: 1 GND (power), 2 IN (in), 3 GND (power), 4 OUT1 (out), 5 NC (hiz), 6 OUT2 (out)

## CMP-0066020-1
designator U?, comment LP5907MFX-3.3/NOPB
250-mA Ultra-Low-Noise, Low-IQ LDO, DBV0005A (SOT-23-5); Alternate Manufacturer: Texas Instruments; Green_Lifecycle: Active; SizeAreaWB_mm2: 14.82; Green_REACh: Passed; U/M: EA; SizeZ_mm: 1.45; SizeX_mm: 2.8; SizeY_mm: 2.9; SizeArea_mm2: 8.12; CompType: IC
footprint DBV0005A_N (SOT23, 5-Leads, Body 2.9x1.6mm, Pitch 0.95mm, Lead Span 2.8mm, IPC Medium Density)
footprint DBV0005A_L (SOT23, 5-Leads, Body 2.9x1.6mm, Pitch 0.95mm, Lead Span 2.8mm, IPC High Density)
footprint DBV0005A_M (SOT23, 5-Leads, Body 2.9x1.6mm, Pitch 0.95mm, Lead Span 2.8mm, IPC Low Density)
pins: 1 VIN (power), 2 GND (power), 3 EN (in), 4 N/C, 5 VOUT (power)
1 alternate drawing of the same symbol

## CMP-0066918-2
designator U?, comment TPS7A4700RGWR
36-V, 1-A, 4.17-uVRMS, RF LDO Voltage Regulator, RGW0020A (VQFN-20); Alternate PartNumber: TPS7A4700RGWT; Alternate Manufacturer: Texas Instruments; Green_Lifecycle: Active; SizeAreaWB_mm2: 49.0; Green_REACh: Passed; SizeZ_mm: 1.0; SizeX_mm: 5.0; SizeArea_mm2: 25.0; CompType: IC; AEC Category: Q200; AEC Qualified: N
footprint RGW0020A (QFN, 20-Leads, Body 5x5mm, Pitch 0.65mm, Thermal Pad 3.15x3.15mm, TI Recommended)
pins: 1 OUT (power), 2 NC, 3 SENSE (in), 4 6P4V2, 5 6P4V1, 6 3P2V, 7 GND (power), 8 1P6V, 9 0P8V, 10 0P4V, 11 0P2V, 12 0P1V, 13 EN (in), 14 NR (in), 15 IN (power), 16 IN (power), 17 NC, 18 NC, 19 NC, 20 OUT (power), 21 PAD

## CMP-0067444-2
designator U?, comment TXS0104EPWR
4-Bit Bidirectional Voltage-Level Shifter for Open-Drain and Push-Pull Applications, PW0014A (TSSOP-14); Alternate Manufacturer: Texas Instruments; Green_Lifecycle: Active; SizeAreaWB_mm2: 58.8; Green_REACh: Passed; SizeZ_mm: 1.2; SizeX_mm: 6.4; SizeY_mm: 5.0; SizeArea_mm2: 32.0; CompType: IC; AEC Category: Q200; AEC Qualified: N; Rating: Catalog
footprint PW0014A_N (TSOP, 14-Leads, Body 5x4.4mm, Pitch 0.65mm, IPC Medium Density)
footprint PW0014A_L (TSOP, 14-Leads, Body 5x4.4mm, Pitch 0.65mm, IPC High Density)
footprint PW0014A_M (TSOP, 14-Leads, Body 5x4.4mm, Pitch 0.65mm, IPC Low Density)
pins: 1 VCCA (power), 2 A1 (io), 3 A2 (io), 4 A3 (io), 5 A4 (io), 6 NC, 7 GND (power), 8 OE (in), 9 NC, 10 B4 (io), 11 B3 (io), 12 B2 (io), 13 B1 (io), 14 VCCB (power)

## CMP-0067446-2
designator U?, comment TXS0108ERGYR
8-Bit Bidirectional Voltage-Level Shifter For Open-Drain And Push-Pull Application, RGY0020A (VQFN-20); Alternate Manufacturer: Texas Instruments; Green_Lifecycle: Active; SizeAreaWB_mm2: 24.75; Green_REACh: Passed; U/M: EA; SizeZ_mm: 1.0; SizeX_mm: 3.5; SizeY_mm: 4.5; SizeArea_mm2: 15.75; CompType: IC
footprint RGY0020A (QFN, 20-Leads, Body 4.5x3.5mm, Pitch 0.5mm, Thermal Pad 3.05x2.05mm, TI Recommended)
pins: 1 A1 (io), 2 VCCA (power), 3 A2 (io), 4 A3 (io), 5 A4 (io), 6 A5 (io), 7 A6 (io), 8 A7 (io), 9 A8 (io), 10 OE (in), 11 GND (power), 12 B8 (io), 13 B7 (io), 14 B6 (io), 15 B5 (io), 16 B4 (io), 17 B3 (io), 18 B2 (io), 19 VCCB (power), 20 B1 (io), 21 PAD

## CMP-0077224-1
designator J?, comment AFECLK
Plug, 50 Ohm, Straight, SMT; PartNumber: 0853050232; Manufacturer: Molex; Cert_UL: Y; ContactFinish: Gold; CT: False; Gender: Male; Voltage_V: 335V
footprint Molex_0853050232 (Plug, 50 Ohm, Straight, SMT)
pins: 1, 2

## CMP-0077975-1
designator U?, comment NB7V33MMNTXG
1.8V / 2.5V, 10GHz ÷4 Clock Divider with CML Outputs, QFN-16; Manufacturer: ON Semiconductor
footprint QFN16-3x3MM_0_5 (QFN, 16-Leads, Body 3x3mm, Pitch 0.5mm)
pins: 1 VTCLK, 2 CLK (in), 3 ~{CLK} (in), 4 ~{VTCLK}, 5 VREFAC (power), 6 GND (power), 7 GND (power), 8 GND (power), 9 VCC (power), 10 ~{Q} (out), 11 Q (out), 12 VCC (power), 13 VCC (power), 14 VCC (power), 15 R (in), 16 VCC (power), 17 EP (power)

## CMP-0078922-1
designator R?, comment EXB-28VR000X
RES ARRAY 4 RES ZERO OHM 0804; Manufacturer: Panasonic; Tolerance_%: 5%; Value_Code: 0; SizeArea_mm2: 2; AEC Qualified: Y; AEC Category: Q200; Res_ohm: 22; Value: 0; SizeZ_mm: 0.45; Green_REACh: Passed; EIA_Code: E24; TempCo: 200 ppm/C; AEC Grade: 1; Power_W: 62.5mW; VDC_V: 50V; Value2: 0.0625W; Green_Lifecycle: Active; CompType: Resistor
footprint 0804-8 (SMD, 8-Leads, Body 2x1mm)
pins: 1, 2, 3, 4, 5, 6, 7, 8

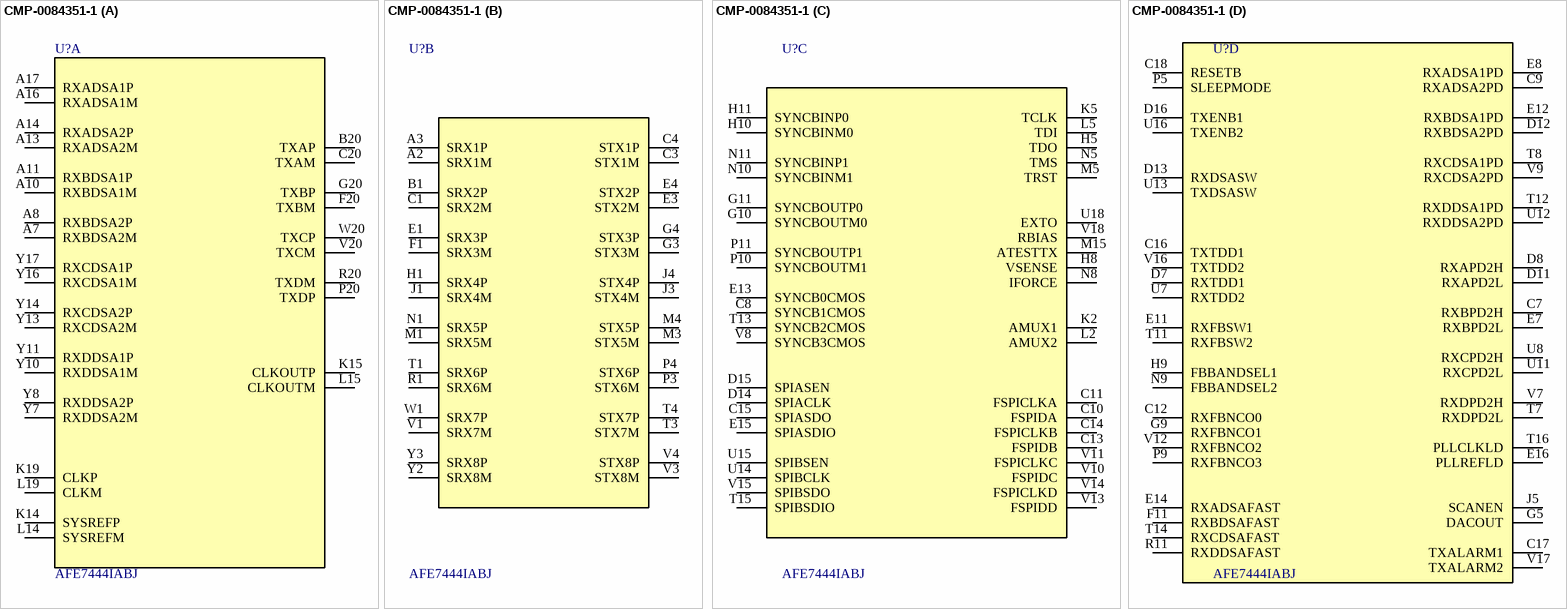
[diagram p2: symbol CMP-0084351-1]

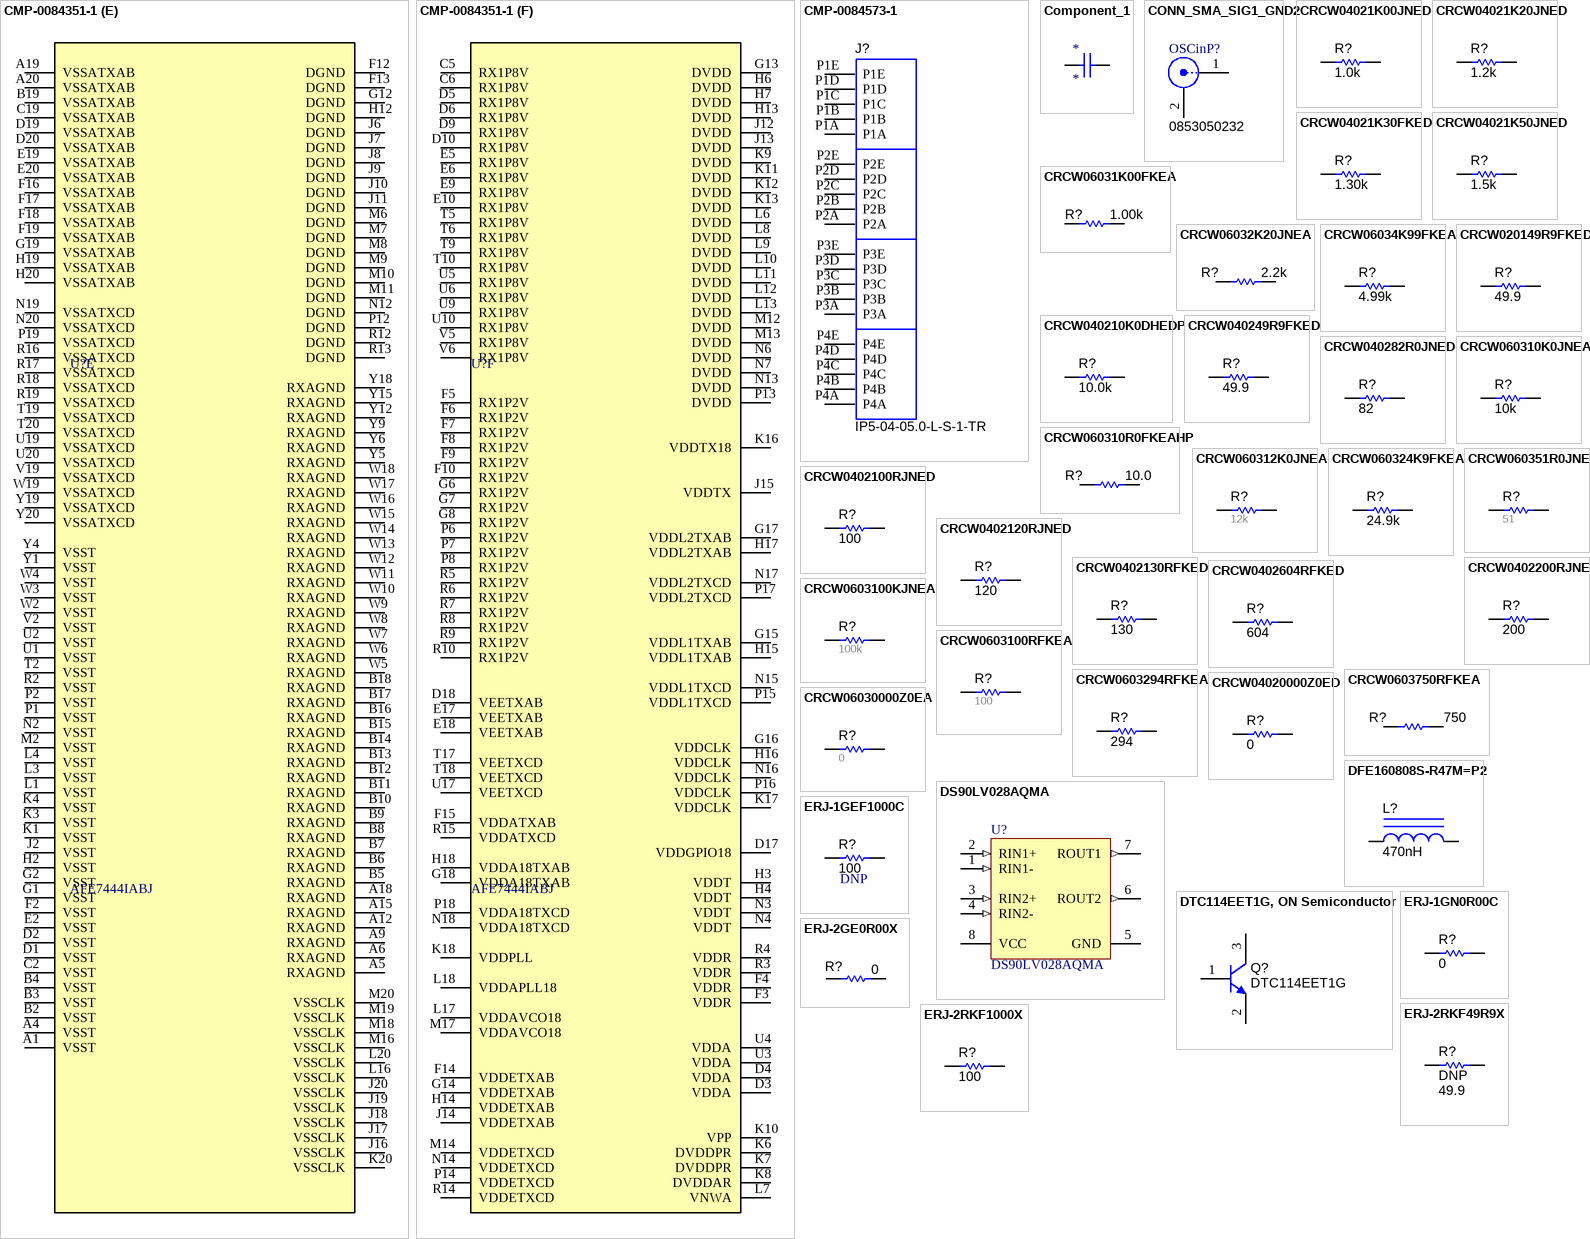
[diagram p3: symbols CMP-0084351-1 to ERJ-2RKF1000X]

## CMP-0084351-1
designator U?, comment AFE7444IABJ
Quad-Channel RF Sampling Transceiver with 14-bit 9-GSPS DACs and 14-bit 3-GSPS ADCs, ABJ0400A (DSBGA-400); Manufacturer: Texas Instruments; SizeY_mm: 17; AEC Qualified: N; CompType: IC; SizeZ_mm: 2.65; SizeAreaWB_mm2: 361; AEC Category: Q200; SizeArea_mm2: 289
footprint ABJ0400A (BGA, 400-Leads, Body 17.2x17.2mm, Pitch 0.8mm)
part A pins: A7 RXBDSA2M, A8 RXBDSA2P, A10 RXBDSA1M, A11 RXBDSA1P, A13 RXADSA2M, A14 RXADSA2P, A16 RXADSA1M, A17 RXADSA1P, B20 TXAP, C20 TXAM, F20 TXBM, G20 TXBP, K14 SYSREFP, K15 CLKOUTP, K19 CLKP, L14 SYSREFM, L15 CLKOUTM, L19 CLKM, P20 TXDP, R20 TXDM, V20 TXCM, W20 TXCP, Y7 RXDDSA2M, Y8 RXDDSA2P, Y10 RXDDSA1M, Y11 RXDDSA1P, Y13 RXCDSA2M, Y14 RXCDSA2P, Y16 RXCDSA1M, Y17 RXCDSA1P
part B pins: A2 SRX1M, A3 SRX1P, B1 SRX2P, C1 SRX2M, C3 STX1M, C4 STX1P, E1 SRX3P, E3 STX2M, E4 STX2P, F1 SRX3M, G3 STX3M, G4 STX3P, H1 SRX4P, J1 SRX4M, J3 STX4M, J4 STX4P, M1 SRX5M, M3 STX5M, M4 STX5P, N1 SRX5P, P3 STX6M, P4 STX6P, R1 SRX6M, T1 SRX6P, T3 STX7M, T4 STX7P, V1 SRX7M, V3 STX8M, V4 STX8P, W1 SRX7P, Y2 SRX8M, Y3 SRX8P
part C pins: C8 SYNCB1CMOS, C10 FSPIDA, C11 FSPICLKA, C13 FSPIDB, C14 FSPICLKB, C15 SPIASDO, D14 SPIACLK, D15 SPIASEN, E13 SYNCB0CMOS, E15 SPIASDIO, G10 SYNCBOUTM0, G11 SYNCBOUTP0, H5 TDO, H8 VSENSE, H10 SYNCBINM0, H11 SYNCBINP0, K2 AMUX1 (power), K5 TCLK, L2 AMUX2 (power), L5 TDI, M5 TRST, M15 ATESTTX, N5 TMS, N8 IFORCE, N10 SYNCBINM1, N11 SYNCBINP1, P10 SYNCBOUTM1, P11 SYNCBOUTP1, T13 SYNCB2CMOS, T15 SPIBSDIO, U14 SPIBCLK, U15 SPIBSEN, U18 EXTO, V8 SYNCB3CMOS, V10 FSPIDC, V11 FSPICLKC, V13 FSPIDD, V14 FSPICLKD, V15 SPIBSDO, V18 RBIAS
part D pins: C7 RXBPD2H, C9 RXADSA2PD, C12 RXFBNCO0, C16 TXTDD1, C17 TXALARM1, C18 RESETB, D7 RXTDD1, D8 RXAPD2H, D11 RXAPD2L, D12 RXBDSA2PD, D13 RXDSASW, D16 TXENB1, E7 RXBPD2L, E8 RXADSA1PD, E11 RXFBSW1, E12 RXBDSA1PD, E14 RXADSAFAST, E16 PLLREFLD, F11 RXBDSAFAST, G5 DACOUT, G9 RXFBNCO1, H9 FBBANDSEL1, J5 SCANEN, N9 FBBANDSEL2, P5 SLEEPMODE, P9 RXFBNCO3, R11 RXDDSAFAST, T7 RXDPD2L, T8 RXCDSA1PD, T11 RXFBSW2, T12 RXDDSA1PD, T14 RXCDSAFAST, T16 PLLCLKLD, U7 RXTDD2, U8 RXCPD2H, U11 RXCPD2L, U12 RXDDSA2PD, U13 TXDSASW, U16 TXENB2, V7 RXDPD2H, V9 RXCDSA2PD, V12 RXFBNCO2, V16 TXTDD2, V17 TXALARM2
part E pins: A1 VSST (power), A4 VSST (power), A5 RXAGND (power), A6 RXAGND (power), A9 RXAGND (power), A12 RXAGND (power), A15 RXAGND (power), A18 RXAGND (power), A19 VSSATXAB (power), A20 VSSATXAB (power), B2 VSST (power), B3 VSST (power), B4 VSST (power), B5 RXAGND (power), B6 RXAGND (power), B7 RXAGND (power), B8 RXAGND (power), B9 RXAGND (power), B10 RXAGND (power), B11 RXAGND (power), B12 RXAGND (power), B13 RXAGND (power), B14 RXAGND (power), B15 RXAGND (power), B16 RXAGND (power), B17 RXAGND (power), B18 RXAGND (power), B19 VSSATXAB (power), C2 VSST (power), C19 VSSATXAB (power), D1 VSST (power), D2 VSST (power), D19 VSSATXAB (power), D20 VSSATXAB (power), E2 VSST (power), E19 VSSATXAB (power), E20 VSSATXAB (power), F2 VSST (power), F12 DGND (power), F13 DGND (power), F16 VSSATXAB (power), F17 VSSATXAB (power), F18 VSSATXAB (power), F19 VSSATXAB (power), G1 VSST (power), G2 VSST (power), G12 DGND (power), G19 VSSATXAB (power), H2 VSST (power), H12 DGND (power), H19 VSSATXAB (power), H20 VSSATXAB (power), J2 VSST (power), J6 DGND (power), J7 DGND (power), J8 DGND (power), J9 DGND (power), J10 DGND (power), J11 DGND (power), J16 VSSCLK (power), J17 VSSCLK (power), J18 VSSCLK (power), J19 VSSCLK (power), J20 VSSCLK (power), K1 VSST (power), K3 VSST (power), K4 VSST (power), K20 VSSCLK (power), L1 VSST (power), L3 VSST (power), L4 VSST (power), L16 VSSCLK (power), L20 VSSCLK (power), M2 VSST (power), M6 DGND (power), M7 DGND (power), M8 DGND (power), M9 DGND (power), M10 DGND (power), M11 DGND (power), M16 VSSCLK (power), M18 VSSCLK (power), M19 VSSCLK (power), M20 VSSCLK (power), N2 VSST (power), N12 DGND (power), N19 VSSATXCD (power), N20 VSSATXCD (power), P1 VSST (power), P2 VSST (power), P12 DGND (power), P19 VSSATXCD (power), R2 VSST (power), R12 DGND (power), R13 DGND (power), R16 VSSATXCD (power), R17 VSSATXCD (power), R18 VSSATXCD (power), R19 VSSATXCD (power), T2 VSST (power), T19 VSSATXCD (power), T20 VSSATXCD (power), U1 VSST (power), U2 VSST (power), U19 VSSATXCD (power), U20 VSSATXCD (power), V2 VSST (power), V19 VSSATXCD (power), W2 VSST (power), W3 VSST (power), W4 VSST (power), W5 RXAGND (power), W6 RXAGND (power), W7 RXAGND (power), W8 RXAGND (power), W9 RXAGND (power), W10 RXAGND (power), W11 RXAGND (power), W12 RXAGND (power), W13 RXAGND (power), W14 RXAGND (power), W15 RXAGND (power), W16 RXAGND (power), W17 RXAGND (power), W18 RXAGND (power), W19 VSSATXCD (power), Y1 VSST (power), Y4 VSST (power), Y5 RXAGND (power), Y6 RXAGND (power), Y9 RXAGND (power), Y12 RXAGND (power), Y15 RXAGND (power), Y18 RXAGND (power), Y19 VSSATXCD (power), Y20 VSSATXCD (power)
part F pins: C5 RX1P8V (power), C6 RX1P8V (power), D3 VDDA (power), D4 VDDA (power), D5 RX1P8V (power), D6 RX1P8V (power), D9 RX1P8V (power), D10 RX1P8V (power), D17 VDDGPIO18 (power), D18 VEETXAB (power), E5 RX1P8V (power), E6 RX1P8V (power), E9 RX1P8V (power), E10 RX1P8V (power), E17 VEETXAB (power), E18 VEETXAB (power), F3 VDDR (power), F4 VDDR (power), F5 RX1P2V (power), F6 RX1P2V (power), F7 RX1P2V (power), F8 RX1P2V (power), F9 RX1P2V (power), F10 RX1P2V (power), F14 VDDETXAB (power), F15 VDDATXAB (power), G6 RX1P2V (power), G7 RX1P2V (power), G8 RX1P2V (power), G13 DVDD (power), G14 VDDETXAB (power), G15 VDDL1TXAB (power), G16 VDDCLK (power), G17 VDDL2TXAB (power), G18 VDDA18TXAB (power), H3 VDDT (power), H4 VDDT (power), H6 DVDD (power), H7 DVDD (power), H13 DVDD (power), H14 VDDETXAB (power), H15 VDDL1TXAB (power), H16 VDDCLK (power), H17 VDDL2TXAB (power), H18 VDDA18TXAB (power), J12 DVDD (power), J13 DVDD (power), J14 VDDETXAB (power), J15 VDDTX (power), K6 DVDDPR (power), K7 DVDDPR (power), K8 DVDDAR (power), K9 DVDD (power), K10 VPP (power), K11 DVDD (power), K12 DVDD (power), K13 DVDD (power), K16 VDDTX18 (power), K17 VDDCLK (power), K18 VDDPLL (power), L6 DVDD (power), L7 VNWA, L8 DVDD (power), L9 DVDD (power), L10 DVDD (power), L11 DVDD (power), L12 DVDD (power), L13 DVDD (power), L17 VDDAVCO18 (power), L18 VDDAPLL18 (power), M12 DVDD (power), M13 DVDD (power), M14 VDDETXCD (power), M17 VDDAVCO18 (power), N3 VDDT (power), N4 VDDT (power), N6 DVDD (power), N7 DVDD (power), N13 DVDD (power), N14 VDDETXCD (power), N15 VDDL1TXCD (power), N16 VDDCLK (power), N17 VDDL2TXCD (power), N18 VDDA18TXCD (power), P6 RX1P2V (power), P7 RX1P2V (power), P8 RX1P2V (power), P13 DVDD (power), P14 VDDETXCD (power), P15 VDDL1TXCD (power), P16 VDDCLK (power), P17 VDDL2TXCD (power), P18 VDDA18TXCD (power), R3 VDDR (power), R4 VDDR (power), R5 RX1P2V (power), R6 RX1P2V (power), R7 RX1P2V (power), R8 RX1P2V (power), R9 RX1P2V (power), R10 RX1P2V (power), R14 VDDETXCD (power), R15 VDDATXCD (power), T5 RX1P8V (power), T6 RX1P8V (power), T9 RX1P8V (power), T10 RX1P8V (power), T17 VEETXCD (power), T18 VEETXCD (power), U3 VDDA (power), U4 VDDA (power), U5 RX1P8V (power), U6 RX1P8V (power), U9 RX1P8V (power), U10 RX1P8V (power), U17 VEETXCD (power), V5 RX1P8V (power), V6 RX1P8V (power)

## CMP-0084573-1
designator J?, comment IP5-04-05.0-L-S-1-TR
Plug, 4 Ports, TH; Manufacturer: Samtec; Gender: Male; Voltage_V: 200V; ContactFinish: Gold; Row_Count: 1; Current_A: 2.36A; Cert_UL: Y
footprint Samtec_IP5-04-05.0-X-S-X-TR (Plug, 4 Ports, TH)
pins: P1A, P1B, P1C, P1D, P1E, P2A, P2B, P2C, P2D, P2E, P3A, P3B, P3C, P3D, P3E, P4A, P4B, P4C, P4D, P4E

## Component_1
designator *
pins: 1, 2

## CONN_SMA_SIG1_GND2
designator OSCinP?, comment 0853050232
Plug, 50 Ohm, Straight, SMT; Manufacturer: Molex; Cert_UL: Y; ContactFinish: Gold; CT: False; Gender: Male; Voltage_V: 335V
footprint Molex_0853050232 (Plug, 50 Ohm, Straight, SMT)
pins: 1, 2

## CRCW04021K00JNED
designator R?  ValueDisplayed: 1.0k  (hidden comment: CRCW04021K00JNED)
RES, 1.0 k, 5%, 0.063 W, 0402; Manufacturer: Vishay-Dale; CompType: Resistor; Value: 1.0k; Res_ohm: 1000; Value_Code: 1k00; Tolerance_%: 5; Power_W: 0.063; Value2: 0.063W; VDC_V: 50; TempCo: 200 ppm/C; SizeArea_mm2: 0.5; SizeX_mm: 1; SizeZ_mm: 0.6; EIA_Code: E24; U/M: EA; AEC Category: Q200; Green_Lifecycle: Active; Green_REACh: Passed
signal-integrity model Resistor
simulation model Resistor
footprint 0402
footprint 0402M
footprint 0402L
footprint 0402S
pins: 1, 2

## CRCW04021K20JNED
designator R?  ValueDisplayed: 1.2k  (hidden comment: CRCW04021K20JNED)
RES, 1.2 k, 5%, 0.063 W, 0402; Manufacturer: Vishay-Dale; CompType: Resistor; Value: 1.2k; Res_ohm: 1200; Value_Code: 1k20; Tolerance_%: 5; Power_W: 0.063; Value2: 0.063W; VDC_V: 50; TempCo: 200 ppm/C; EIA_Code: E24; U/M: EA; AEC Category: Q200; SizeArea_mm2: 0.5; SizeX_mm: 1; SizeZ_mm: 0.6
signal-integrity model Resistor
simulation model Resistor
footprint 0402
footprint 0402M
footprint 0402L
footprint 0402S
pins: 1, 2

## CRCW04021K30FKED
designator R?  ValueDisplayed: 1.30k  (hidden comment: CRCW04021K30FKED)
RES, 1.30 k, 1%, 0.063 W, 0402; Manufacturer: Vishay-Dale; CompType: Resistor; Value: 1.30k; Res_ohm: 1300; Value_Code: 1k30; Tolerance_%: 1; Power_W: 0.063; Value2: 0.063W; VDC_V: 50; TempCo: 100 ppm/C; SizeArea_mm2: 0.5; SizeZ_mm: 0.6; EIA_Code: E96; U/M: EA; AEC Category: Q200
signal-integrity model Resistor
simulation model Resistor
footprint 0402
footprint 0402M
footprint 0402L
footprint 0402S
pins: 1, 2

## CRCW04021K50JNED
designator R?  ValueDisplayed: 1.5k  (hidden comment: CRCW04021K50JNED)
RES, 1.5 k, 5%, 0.063 W, 0402; Manufacturer: Vishay-Dale; CompType: Resistor; Value: 1.5k; Res_ohm: 1500; Value_Code: 1k50; Tolerance_%: 5; Power_W: 0.063; Value2: 0.063W; VDC_V: 50; TempCo: 200 ppm/C; SizeArea_mm2: 0.5; SizeX_mm: 1; SizeZ_mm: 0.6; EIA_Code: E24; U/M: EA; AEC Category: Q200
signal-integrity model Resistor
simulation model Resistor
footprint 0402
footprint 0402M
footprint 0402L
footprint 0402S
pins: 1, 2

## CRCW06031K00FKEA
designator R?  ValueDisplayed: 1.00k  (hidden comment: CRCW06031K00FKEA)
RES, 1.00 k, 1%, 0.1 W, 0603; Manufacturer: Vishay-Dale; CompType: Resistor; Value: 1.00k; Res_ohm: 1000; Value_Code: 1k00; Tolerance_%: 1; Power_W: 0.1; Value2: 0.1W; VDC_V: 75; TempCo: 100 ppm/C; SizeArea_mm2: 1.28; SizeX_mm: 1.6; SizeY_mm: 0.8; EIA_Code: E96; U/M: EA; AEC Category: Q200
signal-integrity model Resistor
simulation model Resistor
footprint 0603
footprint 0603M
footprint 0603L
footprint 0603_HV
footprint 0603S
pins: 1, 2

## CRCW06032K20JNEA
designator R?  ValueDisplayed: 2.2k  (hidden comment: CRCW06032K20JNEA)
RES, 2.2 k, 5%, 0.1 W, 0603; Manufacturer: Vishay-Dale; CompType: Resistor; Value: 2.2k; Res_ohm: 2200; Value_Code: 2k20; Tolerance_%: 5; Power_W: 0.1; Value2: 0.1W; VDC_V: 75; TempCo: 200 ppm/C; SizeArea_mm2: 1.28; SizeX_mm: 1.6; SizeY_mm: 0.8; SizeZ_mm: 1; EIA_Code: E24; U/M: EA; AEC Category: Q200
signal-integrity model Resistor
simulation model Resistor
footprint 0603
footprint 0603M
footprint 0603L
footprint 0603_HV
footprint 0603S
pins: 1, 2

## CRCW06034K99FKEA
designator R?  ValueDisplayed: 4.99k  (hidden comment: CRCW06034K99FKEA)
RES, 4.99 k, 1%, 0.1 W, 0603; Manufacturer: Vishay-Dale; CompType: Resistor; Value: 4.99k; Res_ohm: 4990; Value_Code: 4k99; Tolerance_%: 1; Power_W: 0.1; Value2: 0.1W; VDC_V: 75; TempCo: 100 ppm/C; SizeArea_mm2: 1.28; SizeX_mm: 1.6; SizeY_mm: 0.8; EIA_Code: E96; U/M: EA; AEC Category: Q200; Green_Lifecycle: Active; Green_REACh: Passed
signal-integrity model Resistor
simulation model Resistor
footprint 0603
footprint 0603M
footprint 0603L
footprint 0603_HV
footprint 0603S
pins: 1, 2

## CRCW020149R9FKED
designator R?  ValueDisplayed: 49.9  (hidden comment: CRCW020149R9FKED)
RES, 49.9, 1%, 0.05 W, 0201; Manufacturer: Vishay-Dale; CompType: Resistor; Value: 49.9; Value_Code: 49R9; Tolerance_%: 1; Power_W: 0.05; Value2: 0.05W; VDC_V: 30; TempCo: 100 ppm/C; SizeArea_mm2: 0.18; SizeX_mm: 0.6; SizeY_mm: 0.3; SizeZ_mm: 0.26; EIA_Code: E96; U/M: EA; AEC Category: Q200; AEC Qualified: N
signal-integrity model Resistor
simulation model Resistor
footprint 0201
footprint 0201M
footprint 0201L
footprint 0201_Silk
pins: 1, 2

## CRCW040210K0DHEDP
designator R?  ValueDisplayed: 10.0k  (hidden comment: CRCW040210K0DHEDP)
RES, 10.0 k, 0.5%, 0.063 W, 0402; Manufacturer: Vishay-Dale; CompType: Resistor; Value: 10.0k; Res_ohm: 10000; Value_Code: 10k0; Tolerance_%: 0.5; Power_W: 0.063; Value2: 0.063W; VDC_V: 50; TempCo: 50 ppm/C; SizeX_mm: 1; SizeZ_mm: 0.6; EIA_Code: E192; U/M: EA; AEC Category: Q200
signal-integrity model Resistor
simulation model Resistor
footprint 0402
footprint 0402M
footprint 0402L
footprint 0402S
pins: 1, 2

## CRCW040249R9FKED
designator R?  ValueDisplayed: 49.9  (hidden comment: CRCW040249R9FKED)
RES, 49.9, 1%, 0.063 W, 0402; Manufacturer: Vishay-Dale; CompType: Resistor; Value: 49.9; Value_Code: 49R9; Tolerance_%: 1; Power_W: 0.063; Value2: 0.063W; VDC_V: 50; TempCo: 100 ppm/C; EIA_Code: E96; U/M: EA; AEC Category: Q200
signal-integrity model Resistor
simulation model Resistor
footprint 0402
footprint 0402M
footprint 0402L
footprint 0402S
pins: 1, 2

## CRCW040282R0JNED
designator R?  ValueDisplayed: 82  (hidden comment: CRCW040282R0JNED)
RES, 82, 5%, 0.063 W, 0402; Manufacturer: Vishay-Dale; CompType: Resistor; Value: 82; Value_Code: 82R0; Tolerance_%: 5; Power_W: 0.063; Value2: 0.063W; VDC_V: 50; TempCo: 200 ppm/C; SizeArea_mm2: 0.5; SizeX_mm: 1; SizeZ_mm: 0.6; EIA_Code: E24; U/M: EA; AEC Category: Q200
signal-integrity model Resistor
simulation model Resistor
footprint 0402
footprint 0402M
footprint 0402L
footprint 0402S
pins: 1, 2

## CRCW060310K0JNEA
designator R?  ValueDisplayed: 10k  (hidden comment: CRCW060310K0JNEA)
RES, 10 k, 5%, 0.1 W, 0603; Manufacturer: Vishay-Dale; CompType: Resistor; Value: 10k; Res_ohm: 10000; Value_Code: 10k0; Tolerance_%: 5; Power_W: 0.1; Value2: 0.1W; VDC_V: 75; TempCo: 200 ppm/C; SizeArea_mm2: 1.28; SizeX_mm: 1.6; SizeY_mm: 0.8; SizeZ_mm: 1; EIA_Code: E24; U/M: EA; AEC Category: Q200
signal-integrity model Resistor
simulation model Resistor
footprint 0603
footprint 0603M
footprint 0603L
footprint 0603_HV
footprint 0603S
pins: 1, 2

## CRCW060310R0FKEAHP
designator R?  ValueDisplayed: 10.0  (hidden comment: CRCW060310R0FKEAHP)
RES, 10.0, 1%, 0.25 W, 0603; Manufacturer: Vishay-Dale; CompType: Resistor; Value: 10.0; Res_ohm: 10; Value_Code: 10R0; Tolerance_%: 1; Power_W: 0.25; Value2: 0.25W; VDC_V: 75; TempCo: 100 ppm/C; SizeArea_mm2: 1.28; SizeX_mm: 1.6; SizeY_mm: 0.8; EIA_Code: E96; U/M: EA; AEC Category: Q200
signal-integrity model Resistor
simulation model Resistor
footprint 0603
footprint 0603M
footprint 0603L
footprint 0603_HV
footprint 0603S
pins: 1, 2

## CRCW060312K0JNEA
designator R?  value 12k  (hidden comment: CRCW060312K0JNEA)
RES, 12k ohm, 5%, 0.1W, 0603; Manufacturer: Vishay-Dale; CompType: Resistor; Tolerance_%: 5; VDC_V: 75; Power_W: 0.1; Res_ohm: 12000; U/M: EA; Value_Code: 12k0; EIA_Code: E24
signal-integrity model Resistor
simulation model Resistor
footprint 0603
footprint 0603M
footprint 0603L
footprint 0603_HV
pins: 1, 2

## CRCW060324K9FKEA
designator R?  ValueDisplayed: 24.9k  (hidden comment: CRCW060324K9FKEA)
RES, 24.9 k, 1%, 0.1 W, 0603; Manufacturer: Vishay-Dale; CompType: Resistor; Value: 24.9k; Res_ohm: 24900; Value_Code: 24k9; Tolerance_%: 1; Power_W: 0.1; Value2: 0.1W; VDC_V: 75; TempCo: 100 ppm/C; SizeArea_mm2: 1.28; SizeX_mm: 1.6; SizeY_mm: 0.8; EIA_Code: E96; U/M: EA; AEC Category: Q200; Green_Lifecycle: Active; Green_REACh: Passed
signal-integrity model Resistor
simulation model Resistor
footprint 0603
footprint 0603M
footprint 0603L
footprint 0603_HV
footprint 0603S
pins: 1, 2

## CRCW060351R0JNEA
designator R?  ValueDisplayed: 51  (hidden comment: CRCW060351R0JNEA)
RES, 51, 5%, 0.1 W, 0603; Manufacturer: Vishay-Dale; CompType: Resistor; Value: 51; Value_Code: 51R0; Tolerance_%: 5; Power_W: 0.1; Value2: 0.1W; VDC_V: 75; TempCo: 200 ppm/C; EIA_Code: E24; U/M: EA; SizeArea_mm2: 1.28; SizeX_mm: 1.6; SizeY_mm: 0.8; SizeZ_mm: 1; AEC Category: Q200
signal-integrity model Resistor
simulation model Resistor
footprint 0603
footprint 0603M
footprint 0603L
footprint 0603_HV
footprint 0603S
pins: 1, 2

## CRCW0402100RJNED
designator R?  ValueDisplayed: 100  (hidden comment: CRCW0402100RJNED)
RES, 100, 5%, 0.063 W, 0402; Manufacturer: Vishay-Dale; CompType: Resistor; Value: 100; Value_Code: 100R; Tolerance_%: 5; Power_W: 0.063; Value2: 0.063W; VDC_V: 50; TempCo: 200 ppm/C; SizeArea_mm2: 0.5; SizeX_mm: 1; SizeZ_mm: 0.6; EIA_Code: E24; U/M: EA; AEC Category: Q200
signal-integrity model Resistor
simulation model Resistor
footprint 0402
footprint 0402M
footprint 0402L
footprint 0402S
pins: 1, 2

## CRCW0402120RJNED
designator R?  ValueDisplayed: 120  (hidden comment: CRCW0402120RJNED)
RES, 120, 5%, 0.063 W, 0402; Manufacturer: Vishay-Dale; CompType: Resistor; Value: 120; Value_Code: 120R; Tolerance_%: 5; Power_W: 0.063; Value2: 0.063W; VDC_V: 50; TempCo: 200 ppm/C; SizeArea_mm2: 0.5; SizeX_mm: 1; SizeZ_mm: 0.6; EIA_Code: E24; U/M: EA; AEC Category: Q200
signal-integrity model Resistor
simulation model Resistor
footprint 0402
footprint 0402M
footprint 0402L
footprint 0402S
pins: 1, 2

## CRCW0402130RFKED
designator R?  ValueDisplayed: 130  (hidden comment: CRCW0402130RFKED)
RES, 130, 1%, 0.063 W, 0402; Manufacturer: Vishay-Dale; CompType: Resistor; Value: 130; Value_Code: 130R; Tolerance_%: 1; Power_W: 0.063; Value2: 0.063W; VDC_V: 50; TempCo: 100 ppm/C; SizeArea_mm2: 0.5; SizeZ_mm: 0.6; EIA_Code: E96; U/M: EA; AEC Category: Q200
signal-integrity model Resistor
simulation model Resistor
footprint 0402
footprint 0402M
footprint 0402L
footprint 0402S
pins: 1, 2

## CRCW0402200RJNED
designator R?  ValueDisplayed: 200  (hidden comment: CRCW0402200RJNED)
RES, 200, 5%, 0.063 W, 0402; Manufacturer: Vishay-Dale; CompType: Resistor; Value: 200; Value_Code: 200R; Tolerance_%: 5; Power_W: 0.063; Value2: 0.063W; VDC_V: 50; TempCo: 200 ppm/C; SizeArea_mm2: 0.5; SizeX_mm: 1; SizeZ_mm: 0.6; EIA_Code: E24; U/M: EA; AEC Category: Q200; Green_Lifecycle: Active; Green_REACh: Passed
signal-integrity model Resistor
simulation model Resistor
footprint 0402
footprint 0402M
footprint 0402L
footprint 0402S
pins: 1, 2

## CRCW0402604RFKED
designator R?  ValueDisplayed: 604  (hidden comment: CRCW0402604RFKED)
RES, 604, 1%, 0.063 W, 0402; Manufacturer: Vishay-Dale; CompType: Resistor; Value: 604; Value_Code: 604R; Tolerance_%: 1; Power_W: 0.063; Value2: 0.063W; VDC_V: 50; TempCo: 100 ppm/C; SizeArea_mm2: 0.5; SizeZ_mm: 0.6; EIA_Code: E96; U/M: EA; AEC Category: Q200
signal-integrity model Resistor
simulation model Resistor
footprint 0402
footprint 0402M
footprint 0402L
footprint 0402S
pins: 1, 2

## CRCW0603100KJNEA
designator R?  ValueDisplayed: 100k  (hidden comment: CRCW0603100KJNEA)
RES, 100 k, 5%, 0.1 W, 0603; Manufacturer: Vishay-Dale; CompType: Resistor; Tolerance_%: 5; VDC_V: 75; Power_W: 0.1; Res_ohm: 100000; Value: 100k; U/M: EA; Value2: 0.1W; EIA_Code: E24; TempCo: 200 ppm/C; SizeArea_mm2: 1.28; SizeX_mm: 1.6; SizeY_mm: 0.8; SizeZ_mm: 1; AEC Category: Q200
signal-integrity model Resistor
simulation model Resistor
footprint 0603
footprint 0603M
footprint 0603L
footprint 0603_HV
footprint 0603S
pins: 1, 2

## CRCW0603100RFKEA
designator R?  ValueDisplayed: 100  (hidden comment: CRCW0603100RFKEA)
RES, 100, 1%, 0.1 W, 0603; Manufacturer: Vishay-Dale; CompType: Resistor; Tolerance_%: 1; VDC_V: 75; Power_W: 0.1; Value: 100; U/M: EA; Value_Code: 100R; Value2: 0.1W; EIA_Code: E96; TempCo: 100 ppm/C; SizeArea_mm2: 1.28; SizeX_mm: 1.6; SizeY_mm: 0.8; AEC Category: Q200
signal-integrity model Resistor
simulation model Resistor
footprint 0603
footprint 0603M
footprint 0603L
footprint 0603_HV
footprint 0603S
pins: 1, 2

## CRCW0603294RFKEA
designator R?  ValueDisplayed: 294  (hidden comment: CRCW0603294RFKEA)
RES, 294, 1%, 0.1 W, 0603; Manufacturer: Vishay-Dale; CompType: Resistor; Value: 294; Value_Code: 294R; Tolerance_%: 1; Power_W: 0.1; Value2: 0.1W; VDC_V: 75; TempCo: 100 ppm/C; SizeArea_mm2: 1.28; SizeX_mm: 1.6; SizeY_mm: 0.8; EIA_Code: E96; U/M: EA; AEC Category: Q200
signal-integrity model Resistor
simulation model Resistor
footprint 0603
footprint 0603M
footprint 0603L
footprint 0603_HV
footprint 0603S
pins: 1, 2

## CRCW0603750RFKEA
designator R?  ValueDisplayed: 750  (hidden comment: CRCW0603750RFKEA)
RES, 750, 1%, 0.1 W, 0603; Manufacturer: Vishay-Dale; CompType: Resistor; Value: 750; Value_Code: 750R; Tolerance_%: 1; Power_W: 0.1; Value2: 0.1W; VDC_V: 75; TempCo: 100 ppm/C; SizeArea_mm2: 1.28; SizeX_mm: 1.6; SizeY_mm: 0.8; EIA_Code: E96; U/M: EA; AEC Category: Q200
signal-integrity model Resistor
simulation model Resistor
footprint 0603
footprint 0603M
footprint 0603L
footprint 0603_HV
footprint 0603S
pins: 1, 2

## CRCW04020000Z0ED
designator R?  ValueDisplayed: 0  (hidden comment: CRCW04020000Z0ED)
RES, 0, 5%, 0.063 W, 0402; Manufacturer: Vishay-Dale; CompType: Resistor; Tolerance_%: 5; VDC_V: 50; Power_W: 0.063; Value: 0; U/M: EA; Value_Code: 0000; Value2: 0.063W; EIA_Code: E24; TempCo: 200 ppm/C; SizeArea_mm2: 0.5; SizeX_mm: 1; SizeZ_mm: 0.6; AEC Category: Q200
signal-integrity model Resistor
simulation model Resistor
footprint 0402
footprint 0402M
footprint 0402L
footprint 0402S
pins: 1, 2

## CRCW06030000Z0EA
designator R?  ValueDisplayed: 0  (hidden comment: CRCW06030000Z0EA)
RES, 0, 5%, 0.1 W, 0603; Manufacturer: Vishay-Dale; CompType: Resistor; Tolerance_%: 5; VDC_V: 75; Power_W: 0.1; Value: 0; U/M: EA; Value_Code: 0000; Value2: 0.1W; EIA_Code: E24; TempCo: 200 ppm/C; SizeArea_mm2: 1.28; SizeX_mm: 1.6; SizeY_mm: 0.8; SizeZ_mm: 1; AEC Category: Q200
signal-integrity model Resistor
simulation model Resistor
footprint 0603
footprint 0603M
footprint 0603L
footprint 0603_HV
footprint 0603S
pins: 1, 2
